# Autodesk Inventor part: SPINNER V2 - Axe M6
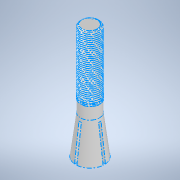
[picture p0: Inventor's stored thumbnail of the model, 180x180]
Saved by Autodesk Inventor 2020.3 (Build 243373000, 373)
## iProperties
Created: 2015-08
Part Number: SPINNER V2 - Axe M6
Material: solidworks materials|Alliage 1060
Document SubType Name: Modeling
Designer: ficho
Density: 2.7 g/cm^3
Appearance: 221,232,255
Sending System: SolidWorks 2014
Last Author: Guillaume
Last Saved: 2015-08-26
Author: ficho
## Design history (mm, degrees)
feature "Enlèvement de matière-Balayage2"
node "Solide1"
